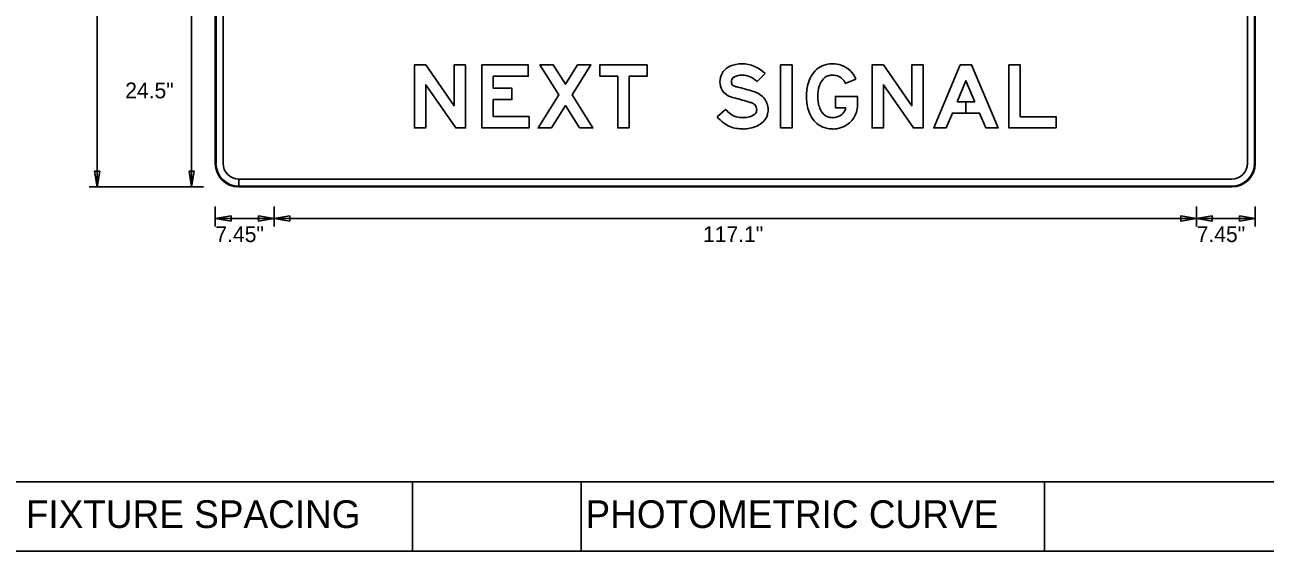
# Model space of a CAD drawing. Extents: x 1274.1 to 1363.1, y 833.5 to 890.6.
# Drawn here: x 1338.12 to 1351.23, y 876.09 to 881.66 of the extents above; entities that cross this region are included whole.
import ezdxf

# ---------------------------------------------------------------- set-up
doc = ezdxf.new("R2010")
doc.units = 0
for name, color, linetype in [('GSBWFill', 7, 'Continuous'), ('GSColorFill', 7, 'Continuous'), ('GSDims', 7, 'Continuous'), ('GSOutline', 7, 'Continuous'), ('SheetLinesMisc2_dp', 7, 'Continuous'), ('TextMinor', 7, 'Continuous')]:
    doc.layers.add(name, color=color, linetype=linetype)

msp = doc.modelspace()

# ---------------------------------------------------------------- linework, layer by layer
at = {"layer": 'GSBWFill'}
for p, q in [((1340.13, 885.692), (1340.13, 880.192)), ((1340.214, 880.192), (1340.214, 885.692)), ((1351.047, 885.692), (1351.047, 880.192)), ((1351.13, 880.192), (1351.13, 885.692)), ((1340.38, 879.942), (1340.38, 880.025)), ((1350.88, 880.025), (1340.381, 880.025)), ((1340.381, 880.025), (1340.381, 879.942)), ((1340.381, 879.942), (1350.88, 879.942))]:
    msp.add_line(p, q, dxfattribs=at)
for points in [[(1342.777, 881.234), (1342.777, 880.567), (1342.674, 880.567), (1342.357, 881.024), (1342.357, 880.567), (1342.237, 880.567), (1342.237, 881.234), (1342.357, 881.234), (1342.657, 880.801), (1342.657, 881.234)], [(1343.45, 880.687), (1343.07, 880.687), (1343.07, 880.866), (1343.267, 880.866), (1343.267, 880.986), (1343.07, 880.986), (1343.07, 881.114), (1343.44, 881.114), (1343.44, 881.234), (1342.95, 881.234), (1342.95, 880.567), (1343.45, 880.567)], [(1343.982, 880.567), (1343.834, 880.803), (1343.685, 880.567), (1343.544, 880.567), (1343.763, 880.916), (1343.564, 881.234), (1343.705, 881.234), (1343.834, 881.029), (1343.962, 881.234), (1344.104, 881.234), (1343.904, 880.916), (1344.124, 880.567)], [(1344.197, 881.114), (1344.387, 881.114), (1344.387, 880.567), (1344.507, 880.567), (1344.507, 881.114), (1344.697, 881.114), (1344.697, 881.234), (1344.197, 881.234)], [(1346.11, 880.567), (1346.11, 881.234), (1346.23, 881.234), (1346.23, 880.567)], [(1347.617, 881.234), (1347.617, 880.567), (1347.514, 880.567), (1347.197, 881.024), (1347.197, 880.567), (1347.077, 880.567), (1347.077, 881.234), (1347.197, 881.234), (1347.497, 880.801), (1347.497, 881.234)], [(1348.164, 880.844), (1348.07, 880.844), (1348.07, 880.724), (1348.214, 880.724), (1348.28, 880.567), (1348.41, 880.567), (1348.13, 881.234), (1348.01, 881.234), (1347.73, 880.567), (1347.86, 880.567), (1347.926, 880.724), (1348.07, 880.724), (1348.07, 880.844), (1347.977, 880.844), (1348.07, 881.066)], [(1349.024, 880.567), (1349.024, 880.684), (1348.644, 880.684), (1348.644, 881.234), (1348.524, 881.234), (1348.524, 880.567)]]:
    msp.add_lwpolyline(points, close=True, dxfattribs=at)
for points in [[(1345.946, 881.142), (1345.861, 881.058)], [(1346.906, 881.082), (1346.794, 881.037)], [(1346.8, 880.78), (1346.69, 880.78), (1346.69, 880.9), (1346.924, 880.9), (1346.924, 880.804)], [(1345.437, 880.685), (1345.528, 880.763)]]:
    msp.add_lwpolyline(points, dxfattribs=at)
for centre, radius, start, end in [((1340.38, 880.192), 0.25, 180, 270), ((1340.38, 880.192), 0.167, 180, 270), ((1350.88, 880.192), 0.25, 270, 0), ((1350.88, 880.192), 0.167, 270, 0)]:
    msp.add_arc(centre, radius, start, end, dxfattribs=at)
for centre, major_axis, start_param, end_param in [((1345.643, 881.059), (0, 0.174), 0.407095, 1.468557), ((1345.7, 880.927), (0, 0.318), 0, 0.407095), ((1345.7, 880.9), (0, 0.345), 5.487912, 6.283185), ((1346.648, 881.004), (0, 0.24), 0.229188, 0.990896), ((1346.659, 880.956), (0, 0.289), 0, 0.229188), ((1346.659, 880.965), (0, 0.28), 5.955089, 6.283185), ((1346.666, 880.985), (0, 0.259), 5.097002, 5.955089), ((1345.659, 881.057), (0, 0.191), 1.468557, 1.941238), ((1345.659, 881.057), (0, 0.0706), 1.468557, 1.941238), ((1345.643, 881.059), (0, 0.0543), 0.407095, 1.468557), ((1345.62, 881.042), (0, 0.029), 1.941238, 2.621157), ((1345.7, 880.927), (0, 0.198), 0, 0.407095), ((1345.7, 880.9), (0, 0.225), 5.487912, 6.283185), ((1346.888, 880.9), (0, 0.505), 1.282161, 1.570796), ((1346.738, 880.945), (0, 0.348), 0.990896, 1.282161), ((1346.738, 880.945), (0, 0.228), 0.990896, 1.282161), ((1346.648, 881.004), (0, 0.12), 0.229188, 0.990896), ((1346.659, 880.956), (0, 0.169), 6.283185, 6.512373), ((1346.659, 880.965), (0, 0.16), 5.955089, 6.283185), ((1346.666, 880.985), (0, 0.139), 5.097002, 5.955089), ((1345.62, 881.042), (0, 0.149), 1.941238, 2.621157), ((1345.689, 881.163), (0, 0.288), 2.621157, 2.899109), ((1345.689, 881.163), (0, 0.168), 2.621157, 2.899109), ((1344.872, 877.859), (0, 3.236), 5.984666, 6.040702), ((1345.73, 880.646), (0, 0.32), 5.812135, 5.984666), ((1345.794, 880.772), (0, 0.178), 5.402773, 5.812135), ((1346.888, 880.9), (0, 0.505), 1.570796, 1.859431), ((1346.888, 880.9), (0, 0.385), 1.282161, 1.570796), ((1346.888, 880.9), (0, 0.385), 1.570796, 1.859431), ((1345.788, 880.989), (0, 0.344), 2.283243, 2.489697), ((1344.872, 877.859), (0, 3.116), 5.984666, 6.040702), ((1345.73, 880.646), (0, 0.2), 5.812135, 5.984666), ((1345.794, 880.772), (0, 0.0579), 5.402773, 5.812135), ((1345.778, 880.759), (0, 0.0794), 4.712389, 5.402773), ((1345.778, 880.759), (0, 0.199), 4.712389, 5.402773), ((1346.738, 880.855), (0, 0.228), 1.859431, 2.150696), ((1346.666, 880.815), (0, 0.139), 3.469689, 4.457885), ((1346.666, 880.815), (0, 0.259), 3.469689, 4.532209), ((1346.726, 880.804), (0, 0.198), 4.532209, 4.712389), ((1345.788, 880.989), (0, 0.464), 2.283243, 2.489697), ((1345.692, 880.862), (0, 0.185), 2.489697, 2.979885), ((1345.712, 880.986), (0, 0.31), 2.979885, 3.141593), ((1345.712, 880.92), (0, 0.245), 3.141593, 3.34483), ((1345.722, 880.872), (0, 0.196), 3.34483, 3.771092), ((1345.811, 880.75), (0, 0.045), 3.771092, 4.424361), ((1345.782, 880.759), (0, 0.0746), 4.424361, 4.712389), ((1345.811, 880.75), (0, 0.165), 3.771092, 4.424361), ((1345.782, 880.759), (0, 0.195), 4.424361, 4.712389), ((1346.738, 880.855), (0, 0.348), 1.859431, 2.150696), ((1346.648, 880.797), (0, 0.24), 2.150696, 2.912405), ((1346.648, 880.797), (0, 0.12), 2.150696, 2.912405), ((1346.659, 880.845), (0, 0.169), 2.912405, 3.141593), ((1346.659, 880.835), (0, 0.16), 3.141593, 3.469689), ((1345.692, 880.862), (0, 0.305), 2.489697, 2.979885), ((1345.712, 880.986), (0, 0.43), 2.979885, 3.141593), ((1345.712, 880.92), (0, 0.365), 3.141593, 3.34483), ((1345.722, 880.872), (0, 0.316), 3.34483, 3.771092), ((1346.659, 880.845), (0, 0.289), 2.912405, 3.141593), ((1346.659, 880.835), (0, 0.28), 3.141593, 3.469689)]:
    msp.add_ellipse(centre, major_axis=major_axis, ratio=0.999995, start_param=start_param, end_param=end_param, dxfattribs=at)
at = {"layer": 'GSColorFill'}
for p, q in [((1340.13, 885.692), (1340.13, 880.192)), ((1340.13, 885.692), (1340.13, 880.192)), ((1340.13, 885.692), (1340.13, 880.192)), ((1340.139, 880.192), (1340.139, 885.692)), ((1340.214, 880.192), (1340.214, 885.692)), ((1351.047, 885.692), (1351.047, 880.192)), ((1351.122, 885.692), (1351.122, 880.192)), ((1351.13, 880.192), (1351.13, 885.692)), ((1351.13, 880.192), (1351.13, 885.692)), ((1351.13, 880.192), (1351.13, 885.692)), ((1340.38, 879.942), (1340.38, 880.025)), ((1350.88, 880.025), (1340.381, 880.025)), ((1340.381, 880.025), (1340.381, 879.942)), ((1340.38, 879.942), (1340.38, 879.95)), ((1350.88, 879.95), (1340.38, 879.95)), ((1340.38, 879.95), (1340.38, 879.942)), ((1340.38, 879.942), (1350.88, 879.942)), ((1340.38, 879.942), (1350.88, 879.942)), ((1340.381, 879.942), (1350.88, 879.942))]:
    msp.add_line(p, q, dxfattribs=at)
for points in [[(1342.777, 881.234), (1342.777, 880.567), (1342.674, 880.567), (1342.357, 881.024), (1342.357, 880.567), (1342.237, 880.567), (1342.237, 881.234), (1342.357, 881.234), (1342.657, 880.801), (1342.657, 881.234)], [(1343.45, 880.687), (1343.07, 880.687), (1343.07, 880.866), (1343.267, 880.866), (1343.267, 880.986), (1343.07, 880.986), (1343.07, 881.114), (1343.44, 881.114), (1343.44, 881.234), (1342.95, 881.234), (1342.95, 880.567), (1343.45, 880.567)], [(1343.982, 880.567), (1343.834, 880.803), (1343.685, 880.567), (1343.544, 880.567), (1343.763, 880.916), (1343.564, 881.234), (1343.705, 881.234), (1343.834, 881.029), (1343.962, 881.234), (1344.104, 881.234), (1343.904, 880.916), (1344.124, 880.567)], [(1344.197, 881.114), (1344.387, 881.114), (1344.387, 880.567), (1344.507, 880.567), (1344.507, 881.114), (1344.697, 881.114), (1344.697, 881.234), (1344.197, 881.234)], [(1346.11, 880.567), (1346.11, 881.234), (1346.23, 881.234), (1346.23, 880.567)], [(1347.617, 881.234), (1347.617, 880.567), (1347.514, 880.567), (1347.197, 881.024), (1347.197, 880.567), (1347.077, 880.567), (1347.077, 881.234), (1347.197, 881.234), (1347.497, 880.801), (1347.497, 881.234)], [(1348.164, 880.844), (1348.07, 880.844), (1348.07, 880.724), (1348.214, 880.724), (1348.28, 880.567), (1348.41, 880.567), (1348.13, 881.234), (1348.01, 881.234), (1347.73, 880.567), (1347.86, 880.567), (1347.926, 880.724), (1348.07, 880.724), (1348.07, 880.844), (1347.977, 880.844), (1348.07, 881.066)], [(1349.024, 880.567), (1349.024, 880.684), (1348.644, 880.684), (1348.644, 881.234), (1348.524, 881.234), (1348.524, 880.567)]]:
    msp.add_lwpolyline(points, close=True, dxfattribs=at)
for points in [[(1345.946, 881.142), (1345.861, 881.058)], [(1346.906, 881.082), (1346.794, 881.037)], [(1346.8, 880.78), (1346.69, 880.78), (1346.69, 880.9), (1346.924, 880.9), (1346.924, 880.804)], [(1345.437, 880.685), (1345.528, 880.763)]]:
    msp.add_lwpolyline(points, dxfattribs=at)
for centre, radius, start, end in [((1340.38, 880.192), 0.25, 180, 270), ((1340.38, 880.192), 0.25, 180, 270), ((1340.38, 880.192), 0.25, 180, 270), ((1340.38, 880.192), 0.242, 180, 270), ((1340.38, 880.192), 0.167, 180, 270), ((1350.88, 880.192), 0.25, 270, 0), ((1350.88, 880.192), 0.25, 270, 0), ((1350.88, 880.192), 0.167, 270, 0), ((1350.88, 880.192), 0.25, 270, 0), ((1350.88, 880.192), 0.242, 270, 0)]:
    msp.add_arc(centre, radius, start, end, dxfattribs=at)
for centre, major_axis, start_param, end_param in [((1345.643, 881.059), (0, 0.174), 0.407095, 1.468557), ((1345.7, 880.927), (0, 0.318), 0, 0.407095), ((1345.7, 880.9), (0, 0.345), 5.487912, 6.283185), ((1346.648, 881.004), (0, 0.24), 0.229188, 0.990896), ((1346.659, 880.956), (0, 0.289), 0, 0.229188), ((1346.659, 880.965), (0, 0.28), 5.955089, 6.283185), ((1346.666, 880.985), (0, 0.259), 5.097002, 5.955089), ((1345.659, 881.057), (0, 0.191), 1.468557, 1.941238), ((1345.659, 881.057), (0, 0.0706), 1.468557, 1.941238), ((1345.643, 881.059), (0, 0.0543), 0.407095, 1.468557), ((1345.62, 881.042), (0, 0.029), 1.941238, 2.621157), ((1345.7, 880.927), (0, 0.198), 0, 0.407095), ((1345.7, 880.9), (0, 0.225), 5.487912, 6.283185), ((1346.888, 880.9), (0, 0.505), 1.282161, 1.570796), ((1346.738, 880.945), (0, 0.348), 0.990896, 1.282161), ((1346.738, 880.945), (0, 0.228), 0.990896, 1.282161), ((1346.648, 881.004), (0, 0.12), 0.229188, 0.990896), ((1346.659, 880.956), (0, 0.169), 6.283185, 6.512373), ((1346.659, 880.965), (0, 0.16), 5.955089, 6.283185), ((1346.666, 880.985), (0, 0.139), 5.097002, 5.955089), ((1345.62, 881.042), (0, 0.149), 1.941238, 2.621157), ((1345.689, 881.163), (0, 0.288), 2.621157, 2.899109), ((1345.689, 881.163), (0, 0.168), 2.621157, 2.899109), ((1344.872, 877.859), (0, 3.236), 5.984666, 6.040702), ((1345.73, 880.646), (0, 0.32), 5.812135, 5.984666), ((1345.794, 880.772), (0, 0.178), 5.402773, 5.812135), ((1346.888, 880.9), (0, 0.505), 1.570796, 1.859431), ((1346.888, 880.9), (0, 0.385), 1.282161, 1.570796), ((1346.888, 880.9), (0, 0.385), 1.570796, 1.859431), ((1345.788, 880.989), (0, 0.344), 2.283243, 2.489697), ((1344.872, 877.859), (0, 3.116), 5.984666, 6.040702), ((1345.73, 880.646), (0, 0.2), 5.812135, 5.984666), ((1345.794, 880.772), (0, 0.0579), 5.402773, 5.812135), ((1345.778, 880.759), (0, 0.0794), 4.712389, 5.402773), ((1345.778, 880.759), (0, 0.199), 4.712389, 5.402773), ((1346.738, 880.855), (0, 0.228), 1.859431, 2.150696), ((1346.666, 880.815), (0, 0.139), 3.469689, 4.457885), ((1346.666, 880.815), (0, 0.259), 3.469689, 4.532209), ((1346.726, 880.804), (0, 0.198), 4.532209, 4.712389), ((1345.788, 880.989), (0, 0.464), 2.283243, 2.489697), ((1345.692, 880.862), (0, 0.185), 2.489697, 2.979885), ((1345.712, 880.986), (0, 0.31), 2.979885, 3.141593), ((1345.712, 880.92), (0, 0.245), 3.141593, 3.34483), ((1345.722, 880.872), (0, 0.196), 3.34483, 3.771092), ((1345.811, 880.75), (0, 0.045), 3.771092, 4.424361), ((1345.782, 880.759), (0, 0.0746), 4.424361, 4.712389), ((1345.811, 880.75), (0, 0.165), 3.771092, 4.424361), ((1345.782, 880.759), (0, 0.195), 4.424361, 4.712389), ((1346.738, 880.855), (0, 0.348), 1.859431, 2.150696), ((1346.648, 880.797), (0, 0.24), 2.150696, 2.912405), ((1346.648, 880.797), (0, 0.12), 2.150696, 2.912405), ((1346.659, 880.845), (0, 0.169), 2.912405, 3.141593), ((1346.659, 880.835), (0, 0.16), 3.141593, 3.469689), ((1345.692, 880.862), (0, 0.305), 2.489697, 2.979885), ((1345.712, 880.986), (0, 0.43), 2.979885, 3.141593), ((1345.712, 880.92), (0, 0.365), 3.141593, 3.34483), ((1345.722, 880.872), (0, 0.316), 3.34483, 3.771092), ((1346.659, 880.845), (0, 0.289), 2.912405, 3.141593), ((1346.659, 880.835), (0, 0.28), 3.141593, 3.469689)]:
    msp.add_ellipse(centre, major_axis=major_axis, ratio=0.999995, start_param=start_param, end_param=end_param, dxfattribs=at)
at = {"layer": 'GSDims'}
for p, q in [((1338.88, 879.942), (1338.88, 885.942)), ((1339.88, 879.942), (1339.88, 881.985)), ((1339.005, 879.942), (1338.797, 879.942)), ((1340.005, 879.942), (1339.005, 879.942)), ((1340.005, 879.942), (1339.797, 879.942)), ((1340.13, 879.734), (1340.13, 879.525)), ((1340.13, 879.734), (1340.13, 879.525)), ((1340.753, 879.734), (1340.753, 879.525)), ((1340.753, 879.734), (1340.753, 879.525)), ((1350.508, 879.734), (1350.508, 879.525)), ((1350.508, 879.734), (1350.508, 879.525)), ((1351.13, 879.734), (1351.13, 879.525)), ((1351.13, 879.734), (1351.13, 879.525)), ((1340.13, 879.609), (1340.753, 879.609)), ((1340.753, 879.609), (1350.508, 879.609)), ((1350.508, 879.609), (1351.13, 879.609))]:
    msp.add_line(p, q, dxfattribs=at)
for points in [[(1338.88, 879.942), (1338.908, 880.109), (1338.853, 880.109)], [(1339.88, 879.942), (1339.908, 880.109), (1339.853, 880.109)], [(1340.13, 879.609), (1340.297, 879.636), (1340.297, 879.581)], [(1340.753, 879.609), (1340.586, 879.636), (1340.586, 879.581)], [(1340.753, 879.609), (1340.919, 879.636), (1340.919, 879.581)], [(1350.508, 879.609), (1350.341, 879.636), (1350.341, 879.581)], [(1350.508, 879.609), (1350.675, 879.636), (1350.675, 879.581)], [(1351.13, 879.609), (1350.964, 879.636), (1350.964, 879.581)]]:
    msp.add_lwpolyline(points, close=True, dxfattribs=at)
at = {"layer": 'GSOutline'}
for p, q in [((1340.13, 885.692), (1340.13, 880.192)), ((1340.214, 885.692), (1340.214, 880.192)), ((1351.047, 880.192), (1351.047, 885.692)), ((1351.13, 880.192), (1351.13, 885.692)), ((1340.38, 880.025), (1350.88, 880.025)), ((1340.38, 879.942), (1350.88, 879.942))]:
    msp.add_line(p, q, dxfattribs=at)
for points in [[(1342.777, 881.234), (1342.777, 880.567), (1342.674, 880.567), (1342.357, 881.024), (1342.357, 880.567), (1342.237, 880.567), (1342.237, 881.234), (1342.357, 881.234), (1342.657, 880.801), (1342.657, 881.234)], [(1343.45, 880.687), (1343.07, 880.687), (1343.07, 880.866), (1343.267, 880.866), (1343.267, 880.986), (1343.07, 880.986), (1343.07, 881.114), (1343.44, 881.114), (1343.44, 881.234), (1342.95, 881.234), (1342.95, 880.567), (1343.45, 880.567)], [(1343.982, 880.567), (1343.834, 880.803), (1343.685, 880.567), (1343.544, 880.567), (1343.763, 880.916), (1343.564, 881.234), (1343.705, 881.234), (1343.834, 881.029), (1343.962, 881.234), (1344.104, 881.234), (1343.904, 880.916), (1344.124, 880.567)], [(1344.197, 881.114), (1344.387, 881.114), (1344.387, 880.567), (1344.507, 880.567), (1344.507, 881.114), (1344.697, 881.114), (1344.697, 881.234), (1344.197, 881.234)], [(1346.11, 880.567), (1346.11, 881.234), (1346.23, 881.234), (1346.23, 880.567)], [(1347.617, 881.234), (1347.617, 880.567), (1347.514, 880.567), (1347.197, 881.024), (1347.197, 880.567), (1347.077, 880.567), (1347.077, 881.234), (1347.197, 881.234), (1347.497, 880.801), (1347.497, 881.234)], [(1347.926, 880.724), (1348.214, 880.724), (1348.28, 880.567), (1348.41, 880.567), (1348.13, 881.234), (1348.01, 881.234), (1347.73, 880.567), (1347.86, 880.567)], [(1349.024, 880.567), (1349.024, 880.684), (1348.644, 880.684), (1348.644, 881.234), (1348.524, 881.234), (1348.524, 880.567)], [(1348.164, 880.844), (1348.07, 881.066), (1347.977, 880.844)]]:
    msp.add_lwpolyline(points, close=True, dxfattribs=at)
for points in [[(1345.946, 881.142), (1345.861, 881.058)], [(1346.906, 881.082), (1346.794, 881.037)], [(1346.8, 880.78), (1346.69, 880.78), (1346.69, 880.9), (1346.924, 880.9), (1346.924, 880.804)], [(1345.437, 880.685), (1345.528, 880.763)]]:
    msp.add_lwpolyline(points, dxfattribs=at)
for centre, radius, start, end in [((1340.38, 880.192), 0.25, 180, 270), ((1340.38, 880.192), 0.167, 180, 270), ((1350.88, 880.192), 0.25, 270, 0), ((1350.88, 880.192), 0.167, 270, 0)]:
    msp.add_arc(centre, radius, start, end, dxfattribs=at)
for centre, major_axis, start_param, end_param in [((1345.643, 881.059), (0, 0.174), 0.407095, 1.468557), ((1345.7, 880.927), (0, 0.318), 0, 0.407095), ((1345.7, 880.9), (0, 0.345), 5.487912, 6.283185), ((1346.648, 881.004), (0, 0.24), 0.229188, 0.990896), ((1346.659, 880.956), (0, 0.289), 0, 0.229188), ((1346.659, 880.965), (0, 0.28), 5.955089, 6.283185), ((1346.666, 880.985), (0, 0.259), 5.097002, 5.955089), ((1345.659, 881.057), (0, 0.191), 1.468557, 1.941238), ((1345.659, 881.057), (0, 0.0706), 1.468557, 1.941238), ((1345.643, 881.059), (0, 0.0543), 0.407095, 1.468557), ((1345.62, 881.042), (0, 0.029), 1.941238, 2.621157), ((1345.7, 880.927), (0, 0.198), 0, 0.407095), ((1345.7, 880.9), (0, 0.225), 5.487912, 6.283185), ((1346.888, 880.9), (0, 0.505), 1.282161, 1.570796), ((1346.738, 880.945), (0, 0.348), 0.990896, 1.282161), ((1346.738, 880.945), (0, 0.228), 0.990896, 1.282161), ((1346.648, 881.004), (0, 0.12), 0.229188, 0.990896), ((1346.659, 880.956), (0, 0.169), 6.283185, 6.512373), ((1346.659, 880.965), (0, 0.16), 5.955089, 6.283185), ((1346.666, 880.985), (0, 0.139), 5.097002, 5.955089), ((1345.62, 881.042), (0, 0.149), 1.941238, 2.621157), ((1345.689, 881.163), (0, 0.288), 2.621157, 2.899109), ((1345.689, 881.163), (0, 0.168), 2.621157, 2.899109), ((1344.872, 877.859), (0, 3.236), 5.984666, 6.040702), ((1345.73, 880.646), (0, 0.32), 5.812135, 5.984666), ((1345.794, 880.772), (0, 0.178), 5.402773, 5.812135), ((1346.888, 880.9), (0, 0.505), 1.570796, 1.859431), ((1346.888, 880.9), (0, 0.385), 1.282161, 1.570796), ((1346.888, 880.9), (0, 0.385), 1.570796, 1.859431), ((1345.788, 880.989), (0, 0.344), 2.283243, 2.489697), ((1344.872, 877.859), (0, 3.116), 5.984666, 6.040702), ((1345.73, 880.646), (0, 0.2), 5.812135, 5.984666), ((1345.794, 880.772), (0, 0.0579), 5.402773, 5.812135), ((1345.778, 880.759), (0, 0.0794), 4.712389, 5.402773), ((1345.778, 880.759), (0, 0.199), 4.712389, 5.402773), ((1346.738, 880.855), (0, 0.228), 1.859431, 2.150696), ((1346.666, 880.815), (0, 0.139), 3.469689, 4.457885), ((1346.666, 880.815), (0, 0.259), 3.469689, 4.532209), ((1346.726, 880.804), (0, 0.198), 4.532209, 4.712389), ((1345.788, 880.989), (0, 0.464), 2.283243, 2.489697), ((1345.692, 880.862), (0, 0.185), 2.489697, 2.979885), ((1345.712, 880.986), (0, 0.31), 2.979885, 3.141593), ((1345.712, 880.92), (0, 0.245), 3.141593, 3.34483), ((1345.722, 880.872), (0, 0.196), 3.34483, 3.771092), ((1345.811, 880.75), (0, 0.045), 3.771092, 4.424361), ((1345.782, 880.759), (0, 0.0746), 4.424361, 4.712389), ((1345.811, 880.75), (0, 0.165), 3.771092, 4.424361), ((1345.782, 880.759), (0, 0.195), 4.424361, 4.712389), ((1346.738, 880.855), (0, 0.348), 1.859431, 2.150696), ((1346.648, 880.797), (0, 0.24), 2.150696, 2.912405), ((1346.648, 880.797), (0, 0.12), 2.150696, 2.912405), ((1346.659, 880.845), (0, 0.169), 2.912405, 3.141593), ((1346.659, 880.835), (0, 0.16), 3.141593, 3.469689), ((1345.692, 880.862), (0, 0.305), 2.489697, 2.979885), ((1345.712, 880.986), (0, 0.43), 2.979885, 3.141593), ((1345.712, 880.92), (0, 0.365), 3.141593, 3.34483), ((1345.722, 880.872), (0, 0.316), 3.34483, 3.771092), ((1346.659, 880.845), (0, 0.289), 2.912405, 3.141593), ((1346.659, 880.835), (0, 0.28), 3.141593, 3.469689)]:
    msp.add_ellipse(centre, major_axis=major_axis, ratio=0.999995, start_param=start_param, end_param=end_param, dxfattribs=at)
at = {"layer": 'SheetLinesMisc2_dp'}
for p, q in [((1331.451, 876.823), (1359.592, 876.823)), ((1342.216, 876.823), (1342.216, 876.088)), ((1344, 876.823), (1344, 876.088)), ((1348.899, 876.823), (1348.899, 876.088)), ((1331.451, 876.088), (1359.592, 876.088))]:
    msp.add_line(p, q, dxfattribs=at)

# ---------------------------------------------------------------- texts
at = {"layer": 'GSDims'}
for s, p in [('24.5"', (1339.178, 880.88)), ('7.45"', (1340.132, 879.359)), ('117.1"', (1345.289, 879.359)), ('7.45"', (1350.51, 879.359))]:
    msp.add_text(s, height=0.1667, dxfattribs=at).set_placement(p)
at = {"layer": 'TextMinor'}
for s, p in [('FIXTURE SPACING', (1338.127, 876.334)), ('PHOTOMETRIC CURVE', (1344.046, 876.334))]:
    msp.add_text(s, height=0.2923, dxfattribs=at).set_placement(p)

doc.saveas('drawing.dxf')
